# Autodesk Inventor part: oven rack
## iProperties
Author: Administrator
Created: 2001-03
Part Number: oven rack
Document SubType Name: Modeling
Designer: Administrator
Control State: 0
Master: False
Checked Out: False
PropertySet Name: Design Tracking Control
Shininess: 60.0
PropertySet Name: _Private Model Information
Density: 0.0
Volumn: 0.0
Area: 0.0
PropertySet Name: Model Information
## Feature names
1. Sweep1
2. Mirror1
3. Extrusion1
4. Rectangular Pattern1
